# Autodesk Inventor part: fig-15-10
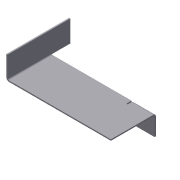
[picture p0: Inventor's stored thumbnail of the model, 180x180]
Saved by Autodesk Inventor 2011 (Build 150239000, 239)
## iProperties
Shininess: 77.0
Angle Display Precision: 2
Document Length Units: 11269
Document Angle Units: 11279
Document Time Units: 11290
Document Mass Units: 11283
Document Length Units Precision: 3
Document Angle Units Precision: 2
Created: 2002-04
Part Number: fig-15-10
Material: Aluminum-6061
Document SubType Name: Sheet Metal
Density: 1 g/cm^3
Sheet Metal Rule: Default
Density: 0.0
Volumn: 0.0
Area: 0.0
PropertySet Name: Model Information
Control State: 0
Master: False
Checked Out: False
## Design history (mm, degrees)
node "Face1"
  sketch "Sketch1"
    geometry: L1 (-49.559, 19.574)-(-49.559, -30.426); L2 (-49.559, -30.426)-(50.441, -30.426); L3 (50.441, -30.426)-(50.441, 19.574); L4 (50.441, 19.574)-(32.941, 19.574); L5 (32.941, 19.574)-(32.941, 4.574); L6 (32.941, 4.574)-(-32.059, 4.574); L7 (-32.059, 4.574)-(-32.059, 19.574); L8 (-32.059, 19.574)-(-49.559, 19.574)
    constraints: 16 end point, 6 parallel, 2 equal length, 1 perpendicular, 1 vertical
    dimensions: "d0" = 100 distance of L1.end L2.end; "d1" = 65 distance of L5.end L6.end; "d2" = 15 distance of L6.end L7.end; "d3" = 50 distance of L1.start L1.end
sketch "Sketch2"
  geometry: L1 (100, 0)-(0, 0) reference; L2 (17.5, 50)-(17.5, 35) reference; L3 (82.5, 50)-(82.5, 0)
  constraints: 2 end point, 1 parallel, 1 point on line
sketch "Sketch3"
  geometry: L1 (81.369, -50)-(0, -50) reference; L2 (17.5, 0)-(17.5, -50)
  constraints: 2 end point, 1 perpendicular, 1 point on line
feature "Fold2" sketch "Sketch3" dims "d8" = 1 (= BendRadius), "d9" = 90 deg, "d10" = 1 (= BendRadius), "d14" = 1 (= BendReliefWidth), "d15" = 0.5 (= BendReliefDepth), "d16" = 2 (= MinimumRemnant), "SeamGap" = 0.01, "Thickness" = 1
sketch "Sketch4"
  geometry: L1 (17.5, 0)-(17.5, -50) reference; L2 (-63.869, -15)-(0, -15) reference; L3 (0, -15)-(17.5, -15)
  constraints: 2 end point, 1 collinear, 1 point on line
feature "Fold3" sketch "Sketch4" dims "d11" = 1 (= BendRadius), "d12" = 90 deg, "d13" = 1 (= BendRadius), "d17" = 1, "d18" = 3, "d19" = 2 (= MinimumRemnant), "SeamGap" = 0.01, "Thickness" = 1
body "Solid1"
face "Plate1" dims "Thickness" = 1
other parameters: "BendRadius" = 1 (= Thickness), "BendReliefWidth" = 1 (= Thickness), "BendReliefDepth" = 0.5 (= 0.5 x Thickness), "CornerReliefSize" = 4 (= 4 x Thickness), "MinimumRemnant" = 2 (= 2 x Thickness), "TransitionRadius" = 1 (= BendRadius), "d4" = 1 (= BendRadius), "JacobiRadiusSize" = 1 (= Thickness), "GapSize" = 1 (= Thickness)
